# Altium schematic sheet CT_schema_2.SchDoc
size 295 x 229 mm
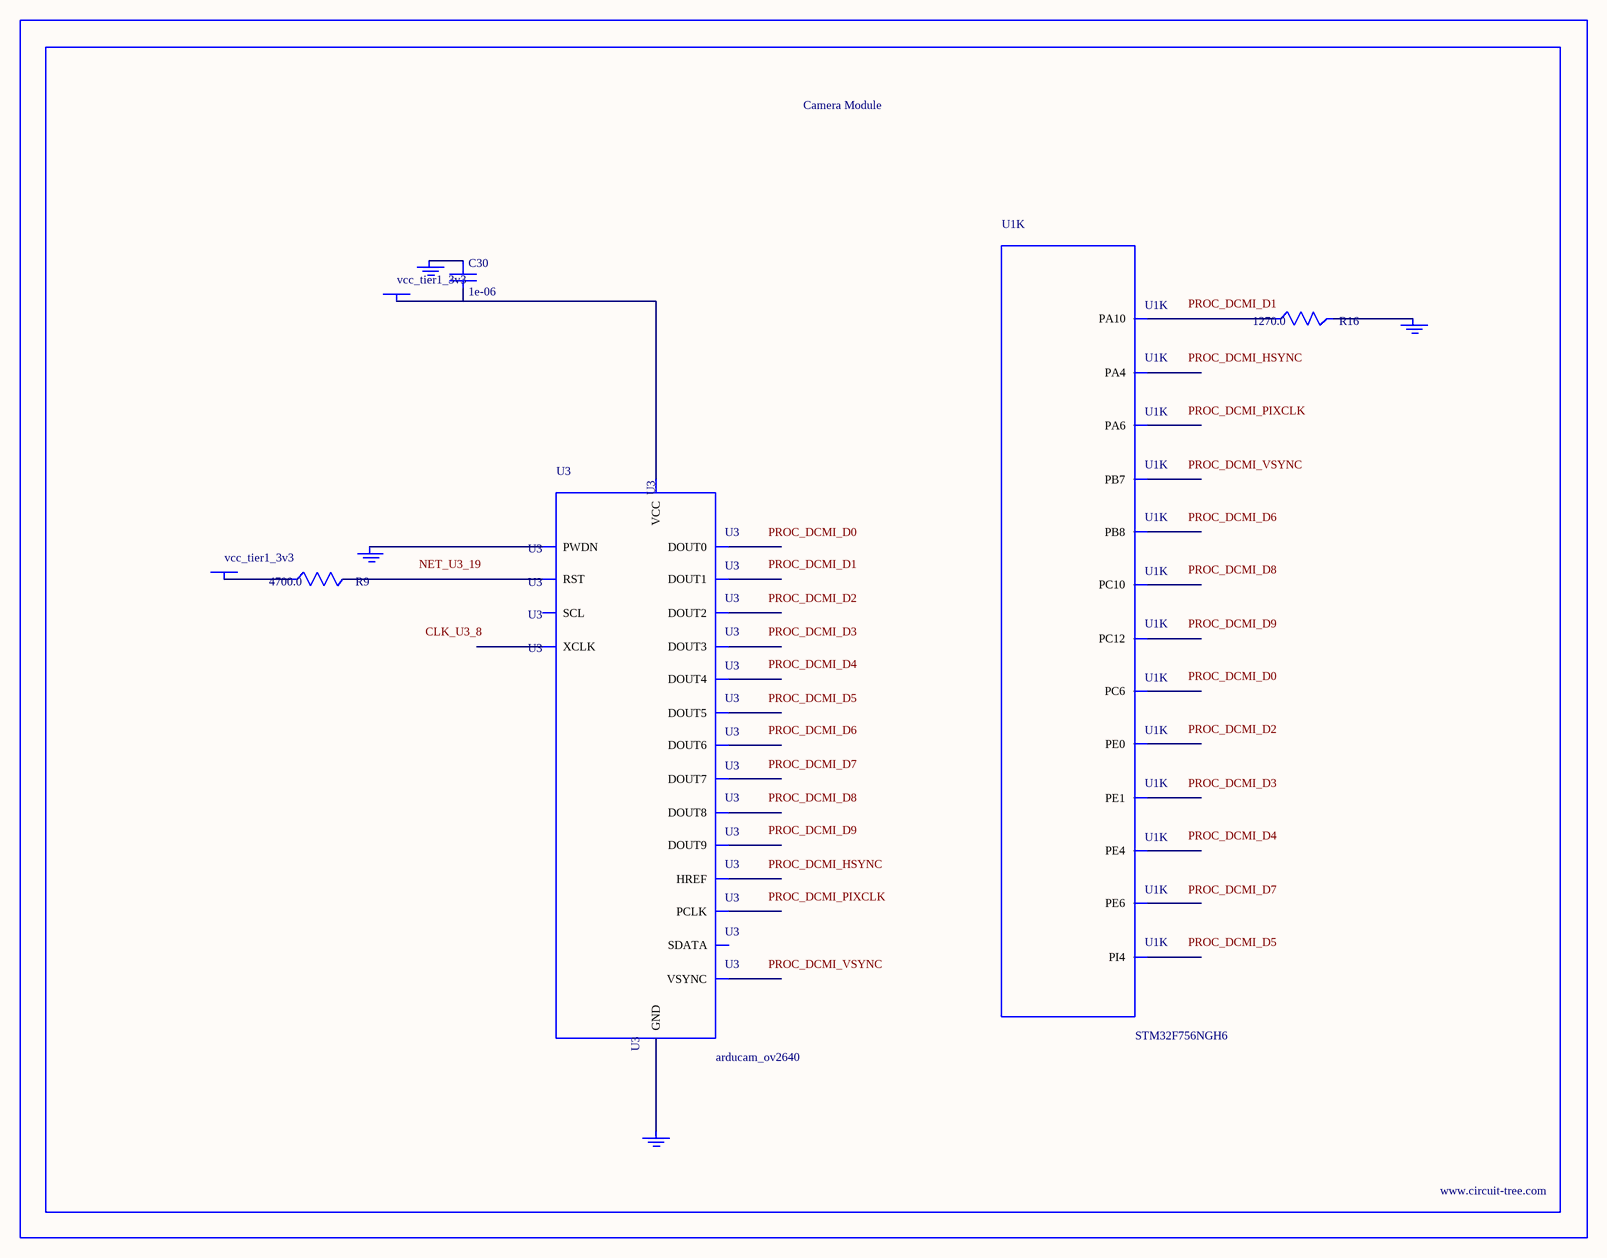
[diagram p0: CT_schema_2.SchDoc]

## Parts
BORDER1  (no value)
C30  1e-06  [C0603]
GND_INSTANCE_1_0  (no value)
GND_INSTANCE_1_1  (no value)
GND_INSTANCE_1_2  (no value)
GND_INSTANCE_1_3  (no value)
POWER_INSTANCE_1_0  vcc_tier1_3v3
POWER_INSTANCE_1_1  vcc_tier1_3v3
R9  4700.0  [R0603]
R16  1270.0  [R0603]
U1  STM32F756NGH6  [TFBGA216]  (part K of 14)
U3  arducam_ov2640  [ARDUCAM]

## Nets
NetC30_1: C30.1 GND_INSTANCE_1_0.0(GND)
NetC30_2: C30.2 POWER_INSTANCE_1_0.0(PWR) U3.1(VCC)
NetGND_INSTANCE_1_1_0: GND_INSTANCE_1_1.0(GND) U3.20(PWDN)
NetGND_INSTANCE_1_2_0: GND_INSTANCE_1_2.0(GND) U3.2(GND)
NetGND_INSTANCE_1_3_0: GND_INSTANCE_1_3.0(GND) R16.2
NetPOWER_INSTANCE_1_1_0: POWER_INSTANCE_1_1.0(PWR) R9.1
NetR9_2: R9.2 U3.19(RST)
NetR16_1: R16.1 U1.D15(PA10)

Not connected (* = marked no-connect by the designer): U1 A1(PE4) A5(PE1) A6(PE0) A7(PB8) A12(PC12) B2(PE6) B5(PB7) B14(PC10) C3(PI4) H15(PC6) N4(PA4) P3(PA6); U3 3(SCL) 4(SDATA) 5(VSYNC) 6(HREF) 7(PCLK) 8(XCLK) 9(DOUT9) 10(DOUT8) 11(DOUT7) 12(DOUT6) 13(DOUT5) 14(DOUT4) 15(DOUT3) 16(DOUT2) 17(DOUT1) 18(DOUT0)

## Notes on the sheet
- Labels drawn without touching a wire or pin: CLK_U3_8, NET_U3_19, PROC_DCMI_D0, PROC_DCMI_D1, PROC_DCMI_D2, PROC_DCMI_D3, PROC_DCMI_D4, PROC_DCMI_D5, PROC_DCMI_D6, PROC_DCMI_D7, PROC_DCMI_D8, PROC_DCMI_D9, PROC_DCMI_HSYNC, PROC_DCMI_PIXCLK, PROC_DCMI_VSYNC

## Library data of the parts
BORDER1 = BORDER_PAGE1
C30 = C0603C105K3RACTU
GND_INSTANCE_1_0-GND_INSTANCE_1_3 = GND
POWER_INSTANCE_1_0 POWER_INSTANCE_1_1 = PWR
R9 = RC0603JR-074K7L
R16 = RC0603FR-071K27L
